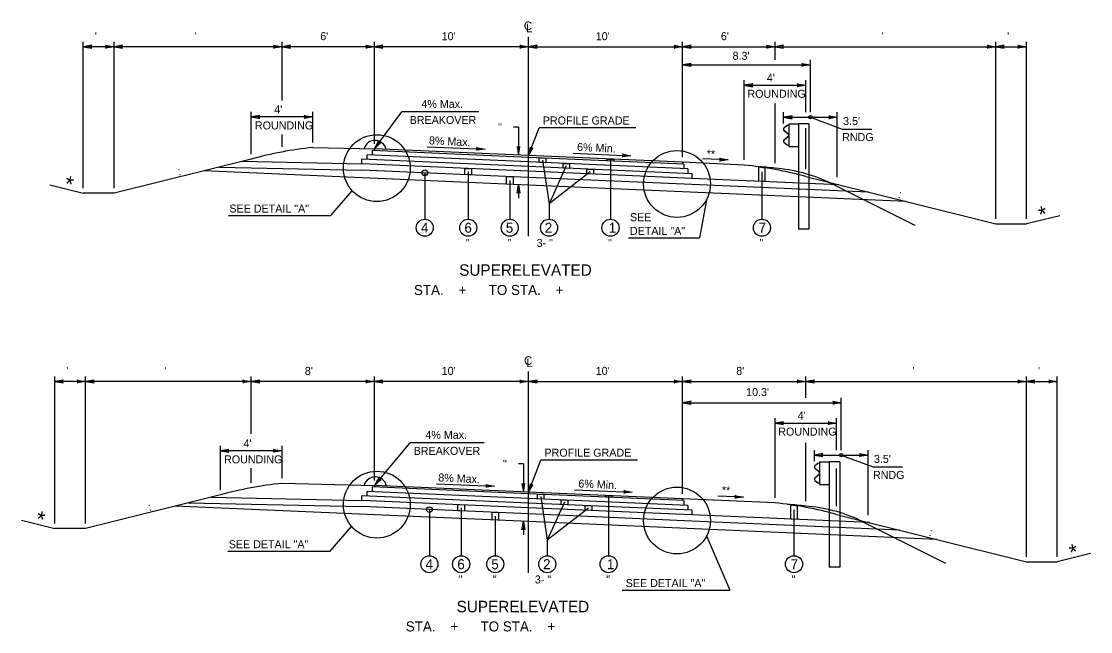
# Model space of a CAD drawing. Extents: x -540 to 1231, y -564 to 421.
# Drawn here: x 493.4 to 680.3, y -247.3 to -140.6 of the extents above; entities that cross this region are included whole.
import ezdxf

# ---------------------------------------------------------------- set-up
doc = ezdxf.new("R2010")
doc.units = 0
doc.layers.add('1', color=7, linetype='Continuous')
doc.layers.add('Des_ Drain_ Ftrs', color=7, linetype='Continuous')

msp = doc.modelspace()

# ---------------------------------------------------------------- linework, layer by layer
at = {"layer": '1'}
for p, q in [((582.04, -178.19), (582.04, -143.31)), ((504.18, -169.81), (504.18, -144.19)), ((509.57, -145.07), (504.18, -145.07)), ((509.57, -169.81), (509.57, -144.19)), ((538.94, -145.07), (509.57, -145.07)), ((538.94, -154.49), (538.94, -144.19)), ((555.1, -145.07), (538.94, -145.07)), ((555.1, -162.04), (555.1, -144.19)), ((582.04, -145.07), (555.1, -145.07)), ((582.04, -145.07), (608.98, -145.07)), ((608.98, -164.39), (608.98, -144.19)), ((608.98, -145.07), (625.15, -145.07)), ((625.15, -147.35), (625.15, -144.19)), ((625.15, -145.07), (663.74, -145.07)), ((663.74, -175.17), (663.74, -144.19)), ((663.74, -145.07), (669.12, -145.07)), ((669.12, -175.17), (669.12, -144.19)), ((631.34, -156.51), (631.34, -147.35)), ((608.98, -148.23), (631.34, -148.23)), ((619.76, -164.86), (619.76, -150.93)), ((630.54, -156.51), (630.54, -150.93)), ((619.76, -151.81), (630.54, -151.81)), ((625.15, -165.41), (625.15, -154.96)), ((533.55, -163.82), (533.55, -156.46)), ((544.33, -161.8), (544.33, -156.46)), ((555.1, -162.92), (559.89, -156.47)), ((573.36, -156.47), (559.89, -156.47)), ((626.65, -158.46), (626.65, -156.51)), ((636.03, -167.85), (636.03, -156.51)), ((544.33, -157.34), (533.55, -157.34)), ((626.65, -157.39), (636.03, -157.39)), ((627.25, -158.86), (626.73, -159.25)), ((627.26, -158.89), (626.75, -159.27)), ((627.56, -158.8), (627.25, -158.86)), ((627.56, -158.83), (627.26, -158.89)), ((627.56, -158.57), (627.56, -162.51)), ((627.56, -158.57), (629.25, -158.57)), ((629.25, -158.57), (629.25, -176.97)), ((631.07, -158.57), (629.25, -158.57)), ((631.07, -158.57), (631.07, -176.97)), ((631.34, -157.39), (636.9, -159.46)), ((538.94, -162.58), (538.94, -160.4)), ((580.3, -159.14), (579.42, -159.14)), ((580.3, -159.14), (580.3, -164.02)), ((582.05, -164.1), (583.92, -159.24)), ((600.84, -159.24), (583.92, -159.24)), ((626.72, -159.68), (627.45, -160.31)), ((627.45, -160.77), (626.72, -161.4)), ((626.74, -159.66), (627.47, -160.29)), ((627.47, -160.79), (626.74, -161.42)), ((627.53, -160.5), (627.53, -160.58)), ((627.56, -160.5), (627.56, -160.58)), ((630.54, -166.39), (630.54, -159.31)), ((636.9, -159.46), (642.06, -159.46)), ((564.32, -162.55), (574.44, -162.99)), ((626.73, -161.83), (627.25, -162.22)), ((626.75, -161.81), (627.26, -162.19)), ((627.25, -162.22), (627.56, -162.28)), ((627.26, -162.19), (627.56, -162.25)), ((627.56, -162.51), (629.25, -162.51)), ((544.33, -162.68), (555.1, -162.92)), ((582.04, -165.21), (553.83, -163.97)), ((553.83, -164.78), (553.83, -163.97)), ((582.04, -164.4), (554.76, -163.2)), ((554.76, -164.01), (554.76, -163.2)), ((582.04, -164.1), (555.1, -162.92)), ((555.1, -163.22), (555.1, -162.92)), ((608.99, -165.27), (582.04, -164.1)), ((609.22, -165.58), (582.04, -164.4)), ((589.84, -163.67), (599.95, -164.11)), ((533.55, -164.69), (509.57, -170.69)), ((527.99, -166.09), (552.91, -166.63)), ((531.95, -165.09), (552.93, -165.55)), ((582.04, -166.01), (552.91, -164.74)), ((552.91, -165.55), (552.91, -164.74)), ((552.91, -164.74), (552.91, -164.74)), ((582.04, -166.82), (552.93, -165.55)), ((609.93, -166.42), (582.04, -165.21)), ((610.63, -167.26), (582.04, -166.01)), ((584.47, -164.91), (585.64, -172.53)), ((588.65, -165.89), (585.64, -172.53)), ((596.38, -164.88), (596.38, -175.22)), ((619.76, -165.74), (608.99, -165.27)), ((608.99, -165.27), (608.99, -165.57)), ((609.22, -165.58), (609.22, -166.39)), ((616.95, -164.86), (612.46, -164.67)), ((582.04, -169.25), (525.25, -166.77)), ((582.04, -167.9), (552.91, -166.63)), ((563.91, -167.11), (563.91, -175.22)), ((571.5, -166.9), (571.5, -175.22)), ((610.64, -168.07), (582.04, -166.82)), ((610.59, -169.15), (582.04, -167.9)), ((592.83, -166.91), (585.64, -172.53)), ((609.93, -166.42), (609.93, -167.23)), ((610.63, -167.26), (610.63, -168.07)), ((610.64, -167.26), (610.63, -167.26)), ((636.29, -169.19), (610.63, -168.07)), ((622.86, -166.94), (622.86, -175.22)), ((626.65, -166.52), (626.65, -166.52)), ((630.54, -167.75), (663.74, -176.05)), ((498.35, -169.23), (504.18, -170.69)), ((578.77, -168.43), (578.77, -175.22)), ((580.3, -169.17), (580.3, -171.54)), ((648.05, -172.13), (582.04, -169.25)), ((641.52, -170.5), (610.59, -169.15)), ((634.54, -168.75), (649.59, -176.28)), ((509.57, -170.69), (504.18, -170.69)), ((547.49, -174.55), (551.23, -170.23)), ((613.14, -171.84), (611.96, -178.48)), ((585.64, -172.53), (585.64, -175.22)), ((529.56, -174.55), (547.49, -174.55)), ((674.95, -174.6), (669.12, -176.05)), ((631.07, -176.97), (629.25, -176.97)), ((663.74, -176.05), (669.12, -176.05)), ((599.55, -178.48), (611.96, -178.48)), ((582.04, -237), (582.04, -201.82)), ((499.19, -228.41), (499.19, -202.7)), ((504.58, -203.58), (499.19, -203.58)), ((504.58, -228.41), (504.58, -202.7)), ((533.55, -203.58), (504.58, -203.58)), ((533.55, -212.75), (533.55, -202.7)), ((555.1, -203.58), (533.55, -203.58)), ((555.1, -220.86), (555.1, -202.7)), ((582.04, -203.58), (555.1, -203.58)), ((582.04, -203.58), (608.98, -203.58)), ((608.98, -223.21), (608.98, -202.7)), ((608.98, -203.58), (630.54, -203.58)), ((630.54, -206.41), (630.54, -202.7)), ((630.54, -203.58), (669.12, -203.58)), ((669.12, -234.23), (669.12, -202.7)), ((669.12, -203.58), (674.51, -203.58)), ((674.51, -234.23), (674.51, -202.7)), ((608.98, -207.29), (636.73, -207.29)), ((636.73, -215.56), (636.73, -206.41)), ((625.15, -223.92), (625.15, -209.98)), ((625.15, -210.86), (635.93, -210.86)), ((635.93, -215.56), (635.93, -209.98)), ((528.16, -222.51), (528.16, -214.82)), ((538.94, -220.5), (538.94, -214.82)), ((555.1, -221.74), (561.32, -214.31)), ((574.29, -214.31), (561.32, -214.31)), ((630.54, -224.52), (630.54, -214.3)), ((538.94, -215.7), (528.16, -215.7)), ((632.04, -217.51), (632.04, -215.56)), ((632.04, -216.44), (641.43, -216.44)), ((636.73, -216.44), (642.29, -218.51)), ((641.43, -226.93), (641.43, -215.56)), ((533.55, -221.28), (533.55, -218.75)), ((581.15, -217.99), (580.27, -217.99)), ((581.15, -217.99), (581.15, -222.87)), ((582.05, -222.92), (584.21, -217.31)), ((601.13, -217.31), (584.21, -217.31)), ((632.11, -218.73), (632.84, -219.37)), ((632.64, -217.91), (632.12, -218.3)), ((632.13, -218.71), (632.86, -219.34)), ((632.65, -217.94), (632.14, -218.32)), ((632.95, -217.85), (632.64, -217.91)), ((632.95, -217.88), (632.65, -217.94)), ((632.95, -217.63), (632.95, -221.56)), ((632.95, -217.63), (634.64, -217.63)), ((634.64, -217.63), (634.64, -236.02)), ((636.46, -217.63), (634.64, -217.63)), ((636.46, -217.63), (636.46, -236.02)), ((642.29, -218.51), (647.45, -218.51)), ((632.84, -219.82), (632.11, -220.45)), ((632.86, -219.84), (632.13, -220.48)), ((632.92, -219.55), (632.92, -219.63)), ((632.95, -219.55), (632.95, -219.63)), ((635.93, -225.4), (635.93, -218.79)), ((538.94, -221.38), (555.1, -221.74)), ((582.04, -223.21), (554.76, -222.02)), ((554.76, -222.83), (554.76, -222.02)), ((582.04, -222.91), (555.1, -221.74)), ((555.1, -221.74), (555.1, -222.04)), ((565.96, -221.46), (576.07, -221.9)), ((590.07, -222.5), (600.18, -222.94)), ((632.12, -220.88), (632.64, -221.27)), ((632.14, -220.86), (632.65, -221.25)), ((632.64, -221.27), (632.95, -221.33)), ((632.65, -221.25), (632.95, -221.3)), ((632.95, -221.56), (634.64, -221.56)), ((528.16, -223.39), (504.58, -229.29)), ((526.56, -223.79), (552.91, -224.37)), ((582.04, -224.83), (552.91, -223.56)), ((552.91, -224.37), (552.91, -223.56)), ((552.91, -223.56), (552.91, -223.56)), ((582.04, -225.64), (552.91, -224.37)), ((582.04, -224.02), (553.83, -222.79)), ((553.83, -223.6), (553.83, -222.79)), ((608.99, -224.09), (582.04, -222.91)), ((609.22, -224.4), (582.04, -223.21)), ((609.93, -225.24), (582.04, -224.02)), ((584.17, -223.71), (585.33, -231.33)), ((596.05, -223.7), (596.05, -234.03)), ((625.15, -224.8), (608.99, -224.09)), ((608.99, -224.39), (608.99, -224.09)), ((619.62, -223.81), (615.13, -223.61)), ((582.04, -228.07), (520.26, -225.37)), ((522.6, -224.78), (552.91, -225.45)), ((582.04, -226.72), (552.91, -225.45)), ((564.71, -225.98), (564.71, -234.03)), ((570.27, -225.69), (570.27, -234.03)), ((610.63, -226.08), (582.04, -224.83)), ((610.63, -226.89), (582.04, -225.64)), ((588.35, -224.69), (585.33, -231.33)), ((592.52, -225.71), (585.33, -231.33)), ((609.22, -224.4), (609.22, -225.21)), ((609.93, -225.24), (609.93, -226.05)), ((610.63, -226.08), (610.63, -226.89)), ((610.63, -226.08), (610.63, -226.08)), ((628.47, -226), (628.47, -234.03)), ((632.04, -225.57), (632.04, -225.57)), ((493.36, -227.83), (499.19, -229.29)), ((576.23, -227.12), (576.23, -234.03)), ((581.15, -228.03), (581.15, -230.39)), ((610.63, -227.97), (582.04, -226.72)), ((653.44, -231.18), (582.04, -228.07)), ((641.68, -228.24), (610.63, -226.89)), ((646.91, -229.55), (610.63, -227.97)), ((635.93, -226.81), (669.12, -235.11)), ((639.93, -227.81), (654.98, -235.33)), ((504.58, -229.29), (499.19, -229.29)), ((547.37, -233.23), (551.11, -228.91)), ((585.33, -231.33), (585.33, -234.03)), ((613.18, -230.56), (617.24, -240.03)), ((529.44, -233.23), (547.37, -233.23)), ((680.34, -233.65), (674.51, -235.11)), ((669.12, -235.11), (674.51, -235.11)), ((636.46, -236.02), (634.64, -236.02)), ((598.45, -240.03), (617.24, -240.03))]:
    msp.add_line(p, q, dxfattribs=at)
for points in [[(583.9, -164.48), (585.05, -164.53), (585.05, -165.34), (583.9, -165.29)], [(570.93, -166.34), (572.08, -166.39), (572.08, -167.47), (570.93, -167.42)], [(588.08, -165.47), (589.22, -165.52), (589.22, -166.33), (588.08, -166.28)], [(595.81, -164.7), (596.95, -164.75), (596.95, -165.05), (595.81, -165)], [(622.34, -166.06), (623.38, -166.22), (623.38, -168.63), (622.34, -168.58)], [(578.2, -167.73), (579.35, -167.78), (579.35, -169.13), (578.2, -169.08)], [(592.25, -166.46), (593.4, -166.51), (593.4, -167.32), (592.25, -167.27)], [(583.6, -223.28), (584.74, -223.33), (584.74, -224.14), (583.6, -224.09)], [(587.77, -224.27), (588.92, -224.32), (588.92, -225.13), (587.77, -225.08)], [(595.48, -223.5), (596.63, -223.55), (596.63, -223.85), (595.48, -223.8)], [(569.69, -225.1), (570.84, -225.15), (570.84, -226.23), (569.69, -226.18)], [(591.95, -225.26), (593.09, -225.31), (593.09, -226.12), (591.95, -226.07)], [(627.9, -225.14), (629.04, -225.31), (629.04, -227.69), (627.9, -227.64)], [(575.66, -226.44), (576.81, -226.49), (576.81, -227.84), (575.66, -227.79)]]:
    msp.add_lwpolyline(points, close=True, dxfattribs=at)
for centre, radius in [((631.34, -157.39), 0.3), ((555.52, -166.28), 5.84), ((608.01, -169.05), 5.84), ((563.91, -167.11), 0.5), ((563.91, -176.7), 1.49), ((571.5, -176.7), 1.49), ((578.77, -176.7), 1.49), ((585.64, -176.7), 1.49), ((596.38, -176.7), 1.49), ((622.86, -176.7), 1.49), ((636.73, -216.44), 0.3), ((555.52, -225.1), 5.84), ((608.01, -227.87), 5.84), ((564.71, -225.98), 0.5), ((564.71, -235.52), 1.49), ((570.27, -235.52), 1.49), ((576.23, -235.52), 1.49), ((585.33, -235.52), 1.49), ((596.05, -235.52), 1.49), ((628.47, -235.52), 1.49)]:
    msp.add_circle(centre, radius, dxfattribs=at)
for centre, radius, start, end in [((626.9, -159.47), 0.278, 126.9799, 229.021), ((626.9, -159.47), 0.249, 126.9799, 229.021), ((627.29, -160.5), 0.249, 0, 49.0365), ((627.29, -160.58), 0.249, 310.9635, 0), ((627.29, -160.5), 0.278, 0, 49.0365), ((627.29, -160.58), 0.278, 310.9635, 0), ((555.2, -163.42), 1.99, 11.9626, 164.1716), ((626.9, -161.61), 0.278, 130.979, 233.0201), ((626.9, -161.61), 0.249, 130.979, 233.0201), ((551.22, -229.52), 67.19, 95.8911, 105.2497), ((612.88, -232.58), 67.19, 74.7602, 84.1188), ((614.33, -266.96), 101.24, 83.8633, 85.6775), ((623.03, -193.59), 27.37, 65.1374, 85.5513), ((632.29, -218.52), 0.278, 126.9799, 229.021), ((632.29, -218.52), 0.249, 126.9799, 229.021), ((555.25, -222.25), 2, 12.248, 163.8639), ((632.29, -220.66), 0.278, 130.979, 233.0201), ((632.29, -220.66), 0.249, 130.979, 233.0201), ((632.68, -219.55), 0.249, 0, 49.0365), ((632.68, -219.63), 0.249, 310.9635, 0), ((632.68, -219.55), 0.278, 0, 49.0365), ((632.68, -219.63), 0.278, 310.9635, 0), ((545.83, -288.22), 67.19, 95.8897, 105.2483), ((618.26, -291.63), 67.19, 74.7602, 84.1188), ((619.72, -326.02), 101.24, 83.8633, 85.6775), ((628.42, -252.64), 27.37, 65.1374, 85.5513)]:
    msp.add_arc(centre, radius, start, end, dxfattribs=at)
at = {"layer": 'Des_ Drain_ Ftrs'}
for points in [[(504.18, -145.07), (505.67, -145.32), (505.37, -145.07), (505.67, -144.82)], [(509.57, -145.07), (508.08, -145.32), (508.37, -145.07), (508.08, -144.82)], [(509.57, -145.07), (511.06, -145.32), (510.76, -145.07), (511.06, -144.82)], [(538.94, -145.07), (537.45, -145.32), (537.74, -145.07), (537.45, -144.82)], [(538.94, -145.07), (540.43, -145.32), (540.13, -145.07), (540.43, -144.82)], [(555.1, -145.07), (553.61, -145.32), (553.91, -145.07), (553.61, -144.82)], [(555.1, -145.07), (556.59, -145.32), (556.3, -145.07), (556.59, -144.82)], [(582.04, -145.07), (580.55, -145.32), (580.85, -145.07), (580.55, -144.82)], [(582.04, -145.07), (583.53, -145.32), (583.24, -145.07), (583.53, -144.82)], [(608.98, -145.07), (607.5, -145.32), (607.79, -145.07), (607.5, -144.82)], [(608.98, -145.07), (610.47, -145.32), (610.18, -145.07), (610.47, -144.82)], [(625.15, -145.07), (623.66, -145.32), (623.96, -145.07), (623.66, -144.82)], [(625.15, -145.07), (626.64, -145.32), (626.34, -145.07), (626.64, -144.82)], [(663.74, -145.07), (662.25, -145.32), (662.54, -145.07), (662.25, -144.82)], [(663.74, -145.07), (665.22, -145.32), (664.93, -145.07), (665.22, -144.82)], [(669.12, -145.07), (667.64, -145.32), (667.93, -145.07), (667.64, -144.82)], [(608.98, -148.23), (610.47, -148.48), (610.17, -148.23), (610.47, -147.99)], [(631.34, -148.23), (629.85, -148.48), (630.15, -148.23), (629.85, -147.99)], [(619.76, -151.81), (621.25, -152.06), (620.95, -151.81), (621.25, -151.56)], [(630.54, -151.81), (629.05, -152.06), (629.34, -151.81), (629.05, -151.56)], [(533.55, -157.34), (535.04, -157.59), (534.74, -157.34), (535.04, -157.09)], [(544.33, -157.34), (542.84, -157.59), (543.13, -157.34), (542.84, -157.09)], [(626.65, -157.39), (628.14, -157.64), (627.84, -157.39), (628.14, -157.14)], [(636.03, -157.39), (634.55, -157.64), (634.84, -157.39), (634.55, -157.14)], [(555.1, -162.92), (556.18, -161.87), (555.81, -161.96), (555.78, -161.58)], [(580.3, -164.02), (580.55, -162.53), (580.3, -162.83), (580.05, -162.53)], [(582.05, -164.1), (582.82, -162.8), (582.48, -162.99), (582.35, -162.62)], [(574.44, -162.99), (572.94, -163.17), (573.24, -162.94), (572.96, -162.68)], [(599.95, -164.11), (598.45, -164.3), (598.76, -164.06), (598.47, -163.8)], [(616.95, -164.86), (615.45, -165.05), (615.76, -164.81), (615.48, -164.55)], [(580.3, -169.17), (580.55, -170.66), (580.3, -170.37), (580.05, -170.66)], [(499.19, -203.58), (500.68, -203.83), (500.38, -203.58), (500.68, -203.34)], [(504.58, -203.58), (503.09, -203.83), (503.38, -203.58), (503.09, -203.34)], [(504.58, -203.58), (506.07, -203.83), (505.77, -203.58), (506.07, -203.34)], [(533.55, -203.58), (532.06, -203.83), (532.36, -203.58), (532.06, -203.34)], [(533.55, -203.58), (535.04, -203.83), (534.74, -203.58), (535.04, -203.34)], [(555.1, -203.58), (553.61, -203.83), (553.91, -203.58), (553.61, -203.34)], [(555.1, -203.58), (556.59, -203.83), (556.3, -203.58), (556.59, -203.34)], [(582.04, -203.58), (580.55, -203.83), (580.85, -203.58), (580.55, -203.34)], [(582.04, -203.58), (583.53, -203.83), (583.24, -203.58), (583.53, -203.34)], [(608.98, -203.58), (607.5, -203.83), (607.79, -203.58), (607.5, -203.34)], [(608.98, -203.58), (610.47, -203.83), (610.18, -203.58), (610.47, -203.34)], [(630.54, -203.58), (629.05, -203.83), (629.34, -203.58), (629.05, -203.34)], [(630.54, -203.58), (632.03, -203.83), (631.73, -203.58), (632.03, -203.34)], [(669.12, -203.58), (667.64, -203.83), (667.93, -203.58), (667.64, -203.34)], [(669.12, -203.58), (670.61, -203.83), (670.32, -203.58), (670.61, -203.34)], [(674.51, -203.58), (673.02, -203.83), (673.32, -203.58), (673.02, -203.34)], [(608.98, -207.29), (610.47, -207.53), (610.18, -207.29), (610.47, -207.04)], [(636.73, -207.29), (635.24, -207.53), (635.54, -207.29), (635.24, -207.04)], [(625.15, -210.86), (626.64, -211.11), (626.34, -210.86), (626.64, -210.61)], [(635.93, -210.86), (634.44, -211.11), (634.73, -210.86), (634.44, -210.61)], [(528.16, -215.7), (529.65, -215.95), (529.35, -215.7), (529.65, -215.45)], [(538.94, -215.7), (537.45, -215.95), (537.74, -215.7), (537.45, -215.45)], [(632.04, -216.44), (633.53, -216.69), (633.23, -216.44), (633.53, -216.19)], [(641.43, -216.44), (639.94, -216.69), (640.23, -216.44), (639.94, -216.19)], [(555.1, -221.74), (556.24, -220.75), (555.86, -220.82), (555.86, -220.44)], [(576.07, -221.9), (574.57, -222.08), (574.88, -221.85), (574.6, -221.59)], [(581.15, -222.87), (581.4, -221.39), (581.15, -221.68), (580.9, -221.39)], [(582.05, -222.92), (582.82, -221.62), (582.48, -221.8), (582.35, -221.44)], [(600.18, -222.94), (598.69, -223.12), (598.99, -222.89), (598.71, -222.63)], [(619.62, -223.81), (618.12, -224), (618.43, -223.76), (618.14, -223.5)], [(581.15, -228.03), (581.4, -229.51), (581.15, -229.22), (580.9, -229.51)]]:
    msp.add_lwpolyline(points, close=True, dxfattribs=at)

# ---------------------------------------------------------------- texts
at = {"layer": '1'}
for s, height, p in [(" '", 1.4, (505.68, -143.92)), ("  '", 1.4, (522.56, -143.92)), ("6'", 1.4, (545.63, -143.92)), ("10'", 1.4, (566.86, -143.92)), ("10'", 1.4, (593.8, -143.92)), ("6'", 1.4, (615.68, -143.92)), ("  '", 1.4, (642.75, -143.92)), (" '", 1.4, (665.23, -143.92)), ("8.3'", 1.4, (617.73, -147.35)), ("4'", 1.4, (623.72, -151.19)), ('ROUNDING', 1.4, (620.33, -153.99)), ('4% Max.', 1.4, (563.31, -155.77)), ("4'", 1.4, (537.58, -156.72)), ('ROUNDING', 1.4, (534.2, -159.52)), ('BREAKOVER', 1.4, (561.26, -158.57)), ('PROFILE GRADE', 1.4, (584.54, -158.66)), ("3.5'", 1.4, (637.06, -158.76)), ('RNDG', 1.4, (636.89, -161.56)), ('SEE DETAIL "A"', 1.4, (529.74, -174.05)), ('SEE', 1.4, (599.78, -175.56)), ('4', 1.75, (563.24, -177.58)), ('6', 1.75, (570.84, -177.58)), ('5', 1.75, (578.08, -177.58)), ('2', 1.75, (584.89, -177.58)), ('1', 1.75, (596.08, -177.58)), ('DETAIL "A"', 1.4, (599.78, -177.96)), ('7', 1.75, (622.27, -177.58)), (' "', 1.4, (570.56, -180.06)), (' "', 1.4, (577.83, -180.06)), ('3- "', 1.4, (583.46, -180.06)), (' "', 1.4, (595.44, -180.06)), (' "', 1.4, (621.91, -180.06)), ('SUPERELEVATED', 2, (569.92, -185.1)), ('STA.    +      TO STA.    +     ', 1.75, (562.01, -188.46)), (" '", 1.4, (500.69, -202.43)), ("  '", 1.4, (517.37, -202.43)), ("8'", 1.4, (542.93, -202.43)), ("10'", 1.4, (566.86, -202.43)), ("10'", 1.4, (593.8, -202.43)), ("8'", 1.4, (618.37, -202.43)), ("  '", 1.4, (648.13, -202.43)), (" '", 1.4, (670.62, -202.43)), ("10.3'", 1.4, (620.1, -206.13)), ("4'", 1.4, (629.11, -210.24)), ('4% Max.', 1.4, (564.01, -213.61)), ('ROUNDING', 1.4, (625.72, -213.04)), ("4'", 1.4, (532.2, -215.09)), ('BREAKOVER', 1.4, (561.96, -216.41)), ('ROUNDING', 1.4, (528.81, -217.89)), ('PROFILE GRADE', 1.4, (584.83, -216.72)), ("3.5'", 1.4, (642.45, -217.81)), ('RNDG', 1.4, (642.28, -220.61)), ('SEE DETAIL "A"', 1.4, (529.62, -232.73)), ('4', 1.75, (564.04, -236.39)), ('6', 1.75, (569.6, -236.39)), ('5', 1.75, (575.54, -236.39)), ('2', 1.75, (584.59, -236.39)), ('1', 1.75, (595.75, -236.39)), ('7', 1.75, (627.88, -236.39)), ('3- "', 1.4, (583.15, -238.88)), (' "', 1.4, (569.32, -238.88)), (' "', 1.4, (575.29, -238.88)), (' "', 1.4, (595.11, -238.88)), ('SEE DETAIL "A"', 1.4, (599.04, -239.52)), ('  "', 1.4, (627.02, -238.88)), ('SUPERELEVATED', 2, (569.47, -243.92)), ('STA.    +      TO STA.    +     ', 1.75, (560.59, -247.27))]:
    msp.add_text(s, height=height, dxfattribs=at).set_placement(p)
for s, height, rotation, p in [('  "', 1.4, 0.1438, (575.69, -159.84)), ('8% Max.', 1.4, 357.3763, (564.61, -162.13)), ('6% Min.', 1.4, 357.3728, (590.51, -163.27)), ('**', 1.4, 357.2162, (613.17, -164.46)), ('*', 2.8, 347.1521, (500.66, -170.26)), (' : ', 1.4, 14.2282, (520.38, -167.71)), (' : ', 1.4, 345.7718, (646.09, -171.35)), ('*', 2.8, 12.8479, (671.59, -175.86)), ('  "', 1.4, 0.1438, (576.54, -218.7)), ('8% Max.', 1.4, 357.376, (566.24, -221.04)), ('6% Min.', 1.4, 357.3731, (590.74, -222.1)), ('**', 1.4, 357.2163, (615.81, -223.25)), (' : ', 1.4, 14.2282, (515.19, -226.35)), ('*', 2.8, 347.1521, (495.68, -228.86)), (' : ', 1.4, 345.7718, (651.47, -230.4)), ('*', 2.8, 12.8479, (676.97, -234.91))]:
    msp.add_text(s, height=height, rotation=rotation, dxfattribs=at).set_placement(p)
at = {"layer": 'Des_ Drain_ Ftrs'}
for s, p in [('C', (581.22, -142.16)), ('L', (581.61, -142.56)), ('C', (581.26, -200.67)), ('L', (581.66, -201.07))]:
    msp.add_text(s, height=1.5, dxfattribs=at).set_placement(p)

doc.saveas('drawing.dxf')
